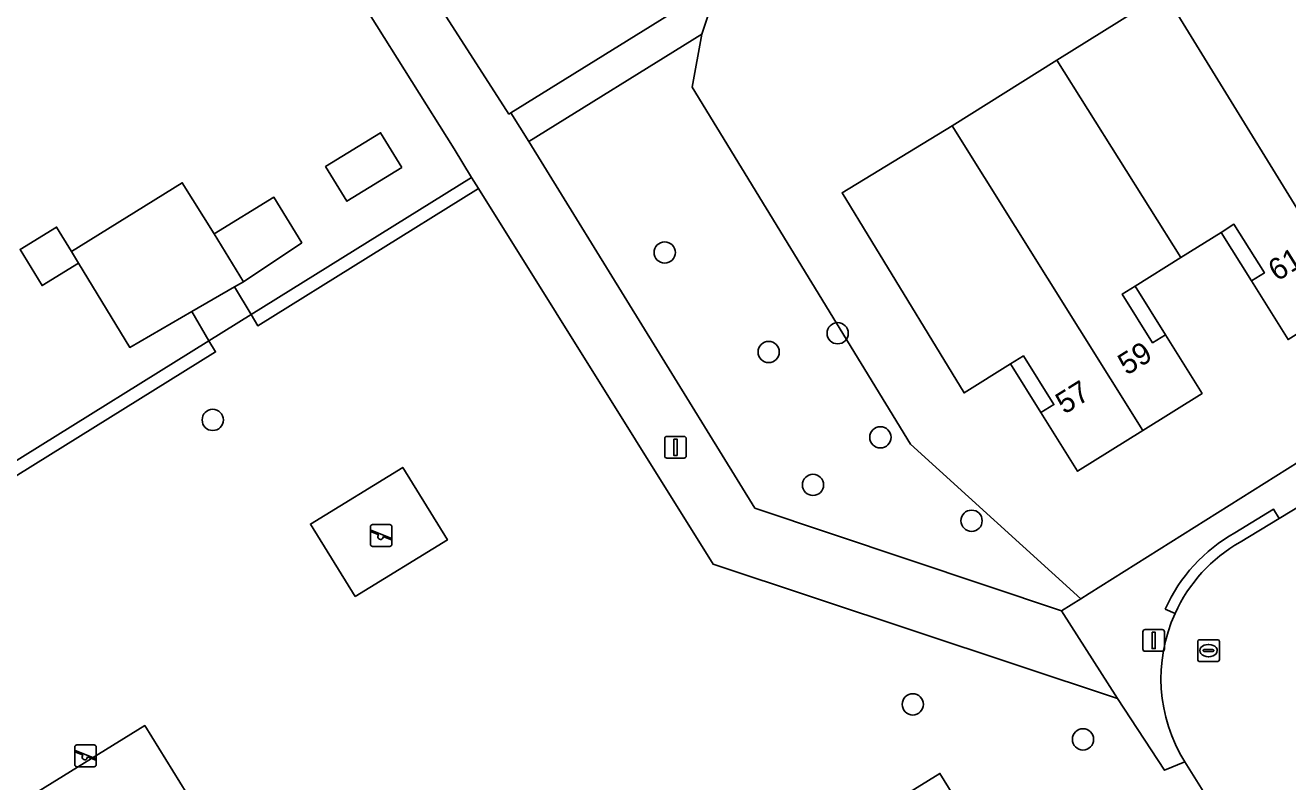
# Model space of a CAD drawing. Extents: x 157767 to 159172, y 387839 to 389425.
# Drawn here: x 158414.7 to 158472.8, y 388070.6 to 388105.4 of the extents above; entities that cross this region are included whole.
import ezdxf

# ---------------------------------------------------------------- set-up
doc = ezdxf.new("R2010")
doc.units = 0
for name, color, linetype in [('IMGEO_Boom', 7, 'Continuous'), ('IMGEO_Erf', 7, 'Continuous'), ('IMGEO_Groenvoorziening', 7, 'Continuous'), ('IMGEO_Haag', 7, 'Continuous'), ('IMGEO_Lichtmast', 7, 'Continuous'), ('IMGEO_Muur', 7, 'Continuous'), ('IMGEO_Pand', 7, 'Continuous'), ('IMGEO_Pand_nummerreeks', 7, 'Continuous'), ('IMGEO_Pand_overbouw', 7, 'Continuous'), ('IMGEO_Rijbaan_lokaal_open', 7, 'Continuous'), ('IMGEO_Rioolput', 7, 'Continuous'), ('IMGEO_Speelvoorziening', 7, 'Continuous'), ('IMGEO_Terreindeel_open', 7, 'Continuous'), ('IMGEO_Voetpad_open', 7, 'Continuous')]:
    doc.layers.add(name, color=color, linetype=linetype)

msp = doc.modelspace()

# ---------------------------------------------------------------- linework, layer by layer
at = {"layer": 'IMGEO_Boom'}
for centre in [(158444.088, 388094.992), (158452.045, 388091.278), (158448.869, 388090.413), (158423.292, 388087.291), (158454.011, 388086.49), (158450.908, 388084.303), (158458.206, 388082.65), (158455.502, 388074.205), (158463.332, 388072.594)]:
    msp.add_circle(centre, 0.489, dxfattribs=at)
at = {"layer": 'IMGEO_Erf'}
for points in [[(158467.833, 388138.446), (158462.988, 388135.417), (158461.467, 388137.85), (158456.637, 388134.83), (158458.158, 388132.397), (158453.327, 388129.377), (158451.806, 388131.81), (158446.965, 388128.783), (158442.085, 388125.732), (158443.495, 388123.312), (158438.652, 388120.284), (158437.232, 388122.698), (158432.406, 388119.68), (158434.152, 388116.851), (158429.021, 388113.683), (158430.343, 388111.582), (158436.919, 388101.362), (158437.013, 388101.42), (158444.186, 388105.865), (158445.929, 388110.2), (158479.147, 388131.262), (158477.004, 388134.657), (158481.831, 388137.704)], [(158474.044, 388122.196), (158472.208, 388125.108), (158467.083, 388121.891), (158468.311, 388119.944), (158466.364, 388118.716), (158461.387, 388115.579), (158460.151, 388117.54), (158455.242, 388114.459), (158447.256, 388109.444), (158445.801, 388105.036), (158445.344, 388102.599), (158455.4, 388086.174), (158463.236, 388079.067), (158463.623, 388079.309), (158475.431, 388086.723)], [(158397.368, 388074.923), (158423.107, 388090.928), (158422.329, 388092.273), (158419.476, 388090.629), (158417.121, 388094.496), (158415.44, 388093.472), (158414.427, 388095.137), (158416.107, 388096.16), (158416.787, 388095.044), (158421.884, 388098.199), (158423.358, 388095.85), (158426.105, 388097.534), (158427.388, 388095.439), (158424.7, 388093.64), (158424.299, 388093.409), (158425.059, 388092.141), (158435.197, 388098.445), (158434.405, 388099.761), (158426.614, 388112.168)], [(158472.768, 388090.984), (158471.083, 388093.681), (158471.677, 388094.053), (158470.277, 388096.29), (158469.683, 388095.919), (158467.828, 388094.76), (158465.731, 388093.449), (158465.138, 388093.079), (158466.537, 388090.84), (158467.13, 388091.21), (158468.815, 388088.513), (158466.085, 388086.807), (158463.082, 388084.93), (158461.396, 388087.627), (158461.991, 388087.999), (158460.591, 388090.237), (158459.997, 388089.865), (158457.86, 388088.529), (158453.619, 388095.492), (158452.248, 388097.742), (158457.309, 388100.824), (158462.129, 388103.837), (158467.083, 388106.934)]]:
    msp.add_lwpolyline(points, dxfattribs=at)
msp.add_lwpolyline([(158431.992, 388098.9), (158429.462, 388097.35), (158428.484, 388098.947), (158431.015, 388100.497)], close=True, dxfattribs=at)
at = {"layer": 'IMGEO_Groenvoorziening'}
for points in [[(158445.344, 388102.599), (158445.801, 388105.036), (158437.83, 388100.097), (158448.238, 388083.238), (158462.351, 388078.513), (158463.236, 388079.067), (158455.4, 388086.174)], [(158435.515, 388097.936), (158435.197, 388098.445), (158425.059, 388092.141), (158425.359, 388091.621)], [(158423.422, 388090.417), (158423.107, 388090.928), (158397.368, 388074.923), (158397.147, 388074.784), (158397.502, 388074.3)], [(158429.851, 388079.17), (158427.783, 388082.499), (158432.033, 388085.102), (158434.091, 388081.768)], [(158423.381, 388068.028), (158418.218, 388064.809), (158414.943, 388069.997), (158420.159, 388073.228)], [(158456.75, 388071.033), (158471.958, 388046.427), (158458.348, 388038.015), (158443.14, 388062.62)], [(158471.958, 388046.427), (158456.75, 388071.033), (158443.14, 388062.62), (158458.348, 388038.015)]]:
    msp.add_lwpolyline(points, close=True, dxfattribs=at)
for points in [[(158464.926, 388074.48), (158446.314, 388080.652), (158435.515, 388097.936), (158425.359, 388091.621), (158425.059, 388092.141), (158423.107, 388090.928), (158423.422, 388090.417), (158397.502, 388074.3), (158401.091, 388069.402)], [(158497.443, 388024.351), (158486.372, 388042.115), (158484.907, 388044.466), (158470.088, 388068.244), (158468.02, 388071.562), (158467.076, 388071.179), (158464.926, 388074.48)]]:
    msp.add_lwpolyline(points, dxfattribs=at)
at = {"layer": 'IMGEO_Haag'}
for points in [[(158435.515, 388097.936), (158435.197, 388098.445), (158425.059, 388092.141), (158425.359, 388091.621)], [(158423.422, 388090.417), (158423.107, 388090.928), (158397.368, 388074.923), (158397.147, 388074.784), (158397.502, 388074.3)]]:
    msp.add_lwpolyline(points, close=True, dxfattribs=at)
at = {"layer": 'IMGEO_Lichtmast'}
for p, q in [((158444.085, 388085.631), (158444.085, 388086.431)), ((158444.085, 388086.431), (158444.085, 388085.631)), ((158444.185, 388086.531), (158444.975, 388086.531)), ((158444.975, 388086.531), (158444.185, 388086.531)), ((158445.075, 388086.431), (158445.075, 388085.631)), ((158445.075, 388085.631), (158445.075, 388086.431)), ((158444.975, 388085.531), (158444.185, 388085.531)), ((158444.185, 388085.531), (158444.975, 388085.531)), ((158466.088, 388076.746), (158466.088, 388077.546)), ((158466.088, 388077.546), (158466.088, 388076.746)), ((158466.188, 388077.646), (158466.978, 388077.646)), ((158466.978, 388077.646), (158466.188, 388077.646)), ((158467.078, 388077.546), (158467.078, 388076.746)), ((158467.078, 388076.746), (158467.078, 388077.546)), ((158466.978, 388076.646), (158466.188, 388076.646)), ((158466.188, 388076.646), (158466.978, 388076.646))]:
    msp.add_line(p, q, dxfattribs=at)
for points in [[(158444.505, 388086.406), (158444.655, 388086.406), (158444.655, 388085.656), (158444.505, 388085.656), (158444.505, 388086.406)], [(158466.508, 388077.521), (158466.658, 388077.521), (158466.658, 388076.771), (158466.508, 388076.771), (158466.508, 388077.521)]]:
    msp.add_lwpolyline(points, dxfattribs=at)
for centre, start, end in [((158444.185, 388086.431), 90, 180), ((158444.185, 388086.431), 90, 180), ((158444.975, 388086.431), 0, 90), ((158444.975, 388086.431), 360, 90), ((158444.185, 388085.631), 180, 270), ((158444.185, 388085.631), 180, 270), ((158444.975, 388085.631), 270, 0), ((158444.975, 388085.631), 270, 0), ((158466.188, 388077.546), 90, 180), ((158466.188, 388077.546), 90, 180), ((158466.978, 388077.546), 0, 90), ((158466.978, 388077.546), 360, 90), ((158466.188, 388076.746), 180, 270), ((158466.188, 388076.746), 180, 270), ((158466.978, 388076.746), 270, 0), ((158466.978, 388076.746), 270, 0)]:
    msp.add_arc(centre, 0.1, start, end, dxfattribs=at)
at = {"layer": 'IMGEO_Muur'}
for points in [[(158426.614, 388112.168), (158434.405, 388099.761)], [(158437.013, 388101.42), (158436.919, 388101.362), (158430.343, 388111.582)]]:
    msp.add_lwpolyline(points, dxfattribs=at)
at = {"layer": 'IMGEO_Pand'}
for points in [[(158467.083, 388106.934), (158475.747, 388092.846), (158478.501, 388094.567), (158476.805, 388097.28), (158476.484, 388097.08), (158475.095, 388099.302), (158475.416, 388099.503), (158477.481, 388100.793), (158473.167, 388107.709), (158471.806, 388109.886)], [(158467.083, 388106.934), (158462.129, 388103.837), (158467.828, 388094.76), (158469.683, 388095.919), (158470.277, 388096.29), (158471.677, 388094.053), (158471.083, 388093.681), (158472.768, 388090.984), (158475.747, 388092.846)], [(158467.828, 388094.76), (158462.129, 388103.837), (158457.309, 388100.824), (158466.085, 388086.807), (158468.815, 388088.513), (158467.13, 388091.21), (158466.537, 388090.84), (158465.138, 388093.079), (158465.731, 388093.449)], [(158466.085, 388086.807), (158457.309, 388100.824), (158452.248, 388097.742), (158453.619, 388095.492), (158457.86, 388088.529), (158459.997, 388089.865), (158460.591, 388090.237), (158461.991, 388087.999), (158461.396, 388087.627), (158463.082, 388084.93)], [(158431.992, 388098.9), (158431.015, 388100.497), (158428.484, 388098.947), (158429.462, 388097.35)], [(158423.358, 388095.85), (158421.884, 388098.199), (158416.787, 388095.044), (158417.121, 388094.496), (158419.476, 388090.629), (158422.329, 388092.273), (158424.299, 388093.409), (158424.7, 388093.64)], [(158423.358, 388095.85), (158424.7, 388093.64), (158427.388, 388095.439), (158426.105, 388097.534)], [(158416.787, 388095.044), (158416.107, 388096.16), (158414.427, 388095.137), (158415.44, 388093.472), (158417.121, 388094.496)]]:
    msp.add_lwpolyline(points, close=True, dxfattribs=at)
at = {"layer": 'IMGEO_Pand_overbouw'}
for points in [[(158471.083, 388093.681), (158471.677, 388094.053), (158470.277, 388096.29), (158469.683, 388095.919)], [(158467.13, 388091.21), (158465.731, 388093.449), (158465.138, 388093.079), (158466.537, 388090.84)], [(158461.396, 388087.627), (158461.991, 388087.999), (158460.591, 388090.237), (158459.997, 388089.865)]]:
    msp.add_lwpolyline(points, close=True, dxfattribs=at)
at = {"layer": 'IMGEO_Rijbaan_lokaal_open'}
for points in [[(158535.283, 388122.156), (158523.084, 388114.526), (158513.779, 388108.72), (158510.479, 388106.661), (158503.775, 388102.469), (158501.451, 388101.016), (158500, 388100.109), (158498.787, 388099.35), (158495.798, 388097.417), (158491.972, 388094.944), (158486.218, 388091.224), (158484.765, 388090.284), (158481.916, 388088.555), (158476.21, 388085.092), (158472.358, 388082.754), (158470.565, 388081.669)], [(158468.02, 388071.562), (158470.088, 388068.244), (158474.521, 388070.623)]]:
    msp.add_lwpolyline(points, dxfattribs=at)
for centre, start, end in [((158474.14, 388075.397), 119.68268, 155.54975), ((158474.139, 388075.394), 155.52491, 212.0553)]:
    msp.add_arc(centre, 7.22, start, end, dxfattribs=at)
at = {"layer": 'IMGEO_Rioolput'}
for p, q in [((158468.609, 388076.253), (158468.609, 388077.105)), ((158468.684, 388077.179), (158469.536, 388077.179)), ((158469.097, 388076.959), (158469.122, 388076.959)), ((158469.61, 388077.105), (158469.61, 388076.253)), ((158468.868, 388076.673), (158468.868, 388076.685)), ((158469.306, 388076.636), (158468.908, 388076.636)), ((158468.911, 388076.722), (158469.309, 388076.722)), ((158469.12, 388076.399), (158469.095, 388076.399)), ((158469.352, 388076.685), (158469.352, 388076.673)), ((158469.536, 388076.179), (158468.684, 388076.179))]:
    msp.add_line(p, q, dxfattribs=at)
for points in [[(158468.609, 388076.253), (158468.609, 388077.105)], [(158468.684, 388077.179), (158469.536, 388077.179)], [(158469.61, 388077.105), (158469.61, 388076.253)], [(158469.536, 388076.179), (158468.684, 388076.179)]]:
    msp.add_lwpolyline(points, dxfattribs=at)
for centre, radius, start, end in [((158468.686, 388077.103), 0.0765, 91.55205, 178.44795), ((158468.686, 388077.103), 0.0765, 91.55205, 178.44795), ((158469.534, 388077.103), 0.0765, 1.55205, 88.44795), ((158469.534, 388077.103), 0.0765, 1.55205, 88.44795), ((158468.686, 388076.255), 0.0765, 181.55205, 268.44795), ((158468.686, 388076.255), 0.0765, 181.55205, 268.44795), ((158468.908, 388076.682), 0.0403, 85.87752, 175.75265), ((158468.905, 388076.672), 0.0366, 178.93798, 274.71019), ((158469.309, 388076.679), 0.043, 264.86636, 352.45326), ((158469.313, 388076.684), 0.0386, 1.73085, 96.63898), ((158469.534, 388076.255), 0.0765, 271.55205, 358.44795), ((158469.534, 388076.255), 0.0765, 271.55205, 358.44795)]:
    msp.add_arc(centre, radius, start, end, dxfattribs=at)
for centre, major_axis, ratio, start_param, end_param in [((158469.096, 388076.679), (-0.387, 0.002), 0.722429, 4.712389, 7.853982), ((158469.121, 388076.679), (-0.39, 0.002), 0.717154, 1.570796, 4.712389)]:
    msp.add_ellipse(centre, major_axis=major_axis, ratio=ratio, start_param=start_param, end_param=end_param, dxfattribs=at)
at = {"layer": 'IMGEO_Speelvoorziening'}
for p, q in [((158430.547, 388081.572), (158430.547, 388082.372)), ((158430.547, 388082.372), (158430.547, 388081.572)), ((158430.93, 388082), (158430.591, 388082.137)), ((158430.616, 388082.197), (158431.492, 388081.844)), ((158430.647, 388082.472), (158431.437, 388082.472)), ((158431.437, 388082.472), (158430.647, 388082.472)), ((158431.537, 388082.372), (158431.537, 388081.572)), ((158431.537, 388081.572), (158431.537, 388082.372)), ((158431.437, 388081.472), (158430.647, 388081.472)), ((158430.647, 388081.472), (158431.437, 388081.472)), ((158431.468, 388081.784), (158431.128, 388081.921)), ((158416.942, 388071.438), (158416.942, 388072.238)), ((158416.942, 388072.238), (158416.942, 388071.438)), ((158417.042, 388072.338), (158417.832, 388072.338)), ((158417.832, 388072.338), (158417.042, 388072.338)), ((158417.932, 388072.238), (158417.932, 388071.438)), ((158417.932, 388071.438), (158417.932, 388072.238)), ((158417.325, 388071.866), (158416.986, 388072.003)), ((158417.011, 388072.063), (158417.887, 388071.71)), ((158417.863, 388071.65), (158417.523, 388071.787)), ((158417.832, 388071.338), (158417.042, 388071.338)), ((158417.042, 388071.338), (158417.832, 388071.338))]:
    msp.add_line(p, q, dxfattribs=at)
for centre, radius, start, end in [((158430.647, 388082.372), 0.1, 90, 180), ((158430.647, 388082.372), 0.1, 90, 180), ((158430.604, 388082.167), 0.0327, 68.07798, 248.07798), ((158431.437, 388082.372), 0.1, 0, 90), ((158431.437, 388082.372), 0.1, 360, 90), ((158430.647, 388081.572), 0.1, 180, 270), ((158430.647, 388081.572), 0.1, 180, 270), ((158431.009, 388081.91), 0.12, 130.99278, 5.16318), ((158431.437, 388081.572), 0.1, 270, 0), ((158431.437, 388081.572), 0.1, 270, 0), ((158431.48, 388081.814), 0.0327, 248.07798, 68.07798), ((158417.042, 388072.238), 0.1, 90, 180), ((158417.042, 388072.238), 0.1, 90, 180), ((158417.832, 388072.238), 0.1, 0, 90), ((158417.832, 388072.238), 0.1, 360, 90), ((158416.999, 388072.033), 0.0327, 68.07798, 248.07798), ((158417.404, 388071.776), 0.12, 130.99278, 5.16318), ((158417.875, 388071.68), 0.0327, 248.07798, 68.07798), ((158417.042, 388071.438), 0.1, 180, 270), ((158417.042, 388071.438), 0.1, 180, 270), ((158417.832, 388071.438), 0.1, 270, 0), ((158417.832, 388071.438), 0.1, 270, 0)]:
    msp.add_arc(centre, radius, start, end, dxfattribs=at)
at = {"layer": 'IMGEO_Terreindeel_open'}
for points in [[(158429.851, 388079.17), (158434.091, 388081.768), (158432.033, 388085.102), (158427.783, 388082.499)], [(158418.218, 388064.809), (158423.381, 388068.028), (158420.159, 388073.228), (158414.943, 388069.997)]]:
    msp.add_lwpolyline(points, close=True, dxfattribs=at)
at = {"layer": 'IMGEO_Voetpad_open'}
for points in [[(158474.829, 388126.761), (158479.863, 388129.936), (158484.896, 388133.11), (158483.974, 388134.309), (158479.147, 388131.262), (158445.929, 388110.2), (158444.186, 388105.865), (158437.013, 388101.42), (158437.83, 388100.097), (158445.801, 388105.036), (158447.256, 388109.444), (158455.242, 388114.459), (158460.151, 388117.54), (158460.113, 388117.601), (158465.107, 388120.75), (158467.036, 388121.966), (158467.083, 388121.891), (158472.208, 388125.108)], [(158430.343, 388111.582), (158429.021, 388113.683), (158427.292, 388116.483), (158423, 388123.434), (158417.299, 388132.666), (158414.79, 388131.043), (158420.56, 388121.91), (158426.614, 388112.168), (158434.405, 388099.761), (158435.197, 388098.445), (158435.515, 388097.936), (158446.314, 388080.652), (158464.926, 388074.48), (158462.351, 388078.513), (158448.238, 388083.238), (158437.83, 388100.097), (158437.013, 388101.42), (158436.919, 388101.362)], [(158424.299, 388093.409), (158422.329, 388092.273), (158423.107, 388090.928), (158425.059, 388092.141)]]:
    msp.add_lwpolyline(points, close=True, dxfattribs=at)
for points in [[(158534.67, 388123.764), (158523.604, 388116.845), (158512.722, 388110.04), (158502.995, 388103.961), (158481.16, 388090.315), (158475.431, 388086.723), (158463.623, 388079.309), (158463.236, 388079.067), (158462.351, 388078.513), (158464.926, 388074.48), (158467.076, 388071.179), (158468.02, 388071.562)], [(158470.317, 388082.103), (158472.099, 388083.182), (158472.358, 388082.754), (158476.21, 388085.092), (158475.954, 388085.519), (158481.66, 388088.983), (158481.916, 388088.555), (158484.765, 388090.284), (158486.218, 388091.224), (158485.95, 388091.645), (158491.704, 388095.364), (158491.972, 388094.944), (158495.798, 388097.417), (158495.533, 388097.84), (158500, 388100.684), (158501.186, 388101.439), (158501.451, 388101.016), (158503.775, 388102.469), (158503.224, 388103.351), (158513.228, 388109.602), (158513.779, 388108.72), (158523.084, 388114.526)], [(158472.358, 388082.754), (158472.099, 388083.182), (158470.317, 388082.103)], [(158470.565, 388081.669), (158472.358, 388082.754)], [(158467.568, 388078.385), (158467.113, 388078.592)], [(158467.113, 388078.592), (158467.568, 388078.385)]]:
    msp.add_lwpolyline(points, dxfattribs=at)
for centre, radius, start, end in [((158474.142, 388075.395), 7.722, 119.69299, 155.54232), ((158474.142, 388075.395), 7.722, 119.69299, 155.54232), ((158474.14, 388075.397), 7.22, 119.68268, 155.54975), ((158474.139, 388075.394), 7.22, 155.52491, 212.0553)]:
    msp.add_arc(centre, radius, start, end, dxfattribs=at)

# ---------------------------------------------------------------- texts
at = {"layer": 'IMGEO_Pand_nummerreeks'}
for s, p in [('61', (158472.261, 388093.639)), ('59', (158465.346, 388089.316)), ('57', (158462.479, 388087.525))]:
    msp.add_text(s, height=1, rotation=32.00449, dxfattribs=at).set_placement(p)

doc.saveas('drawing.dxf')
